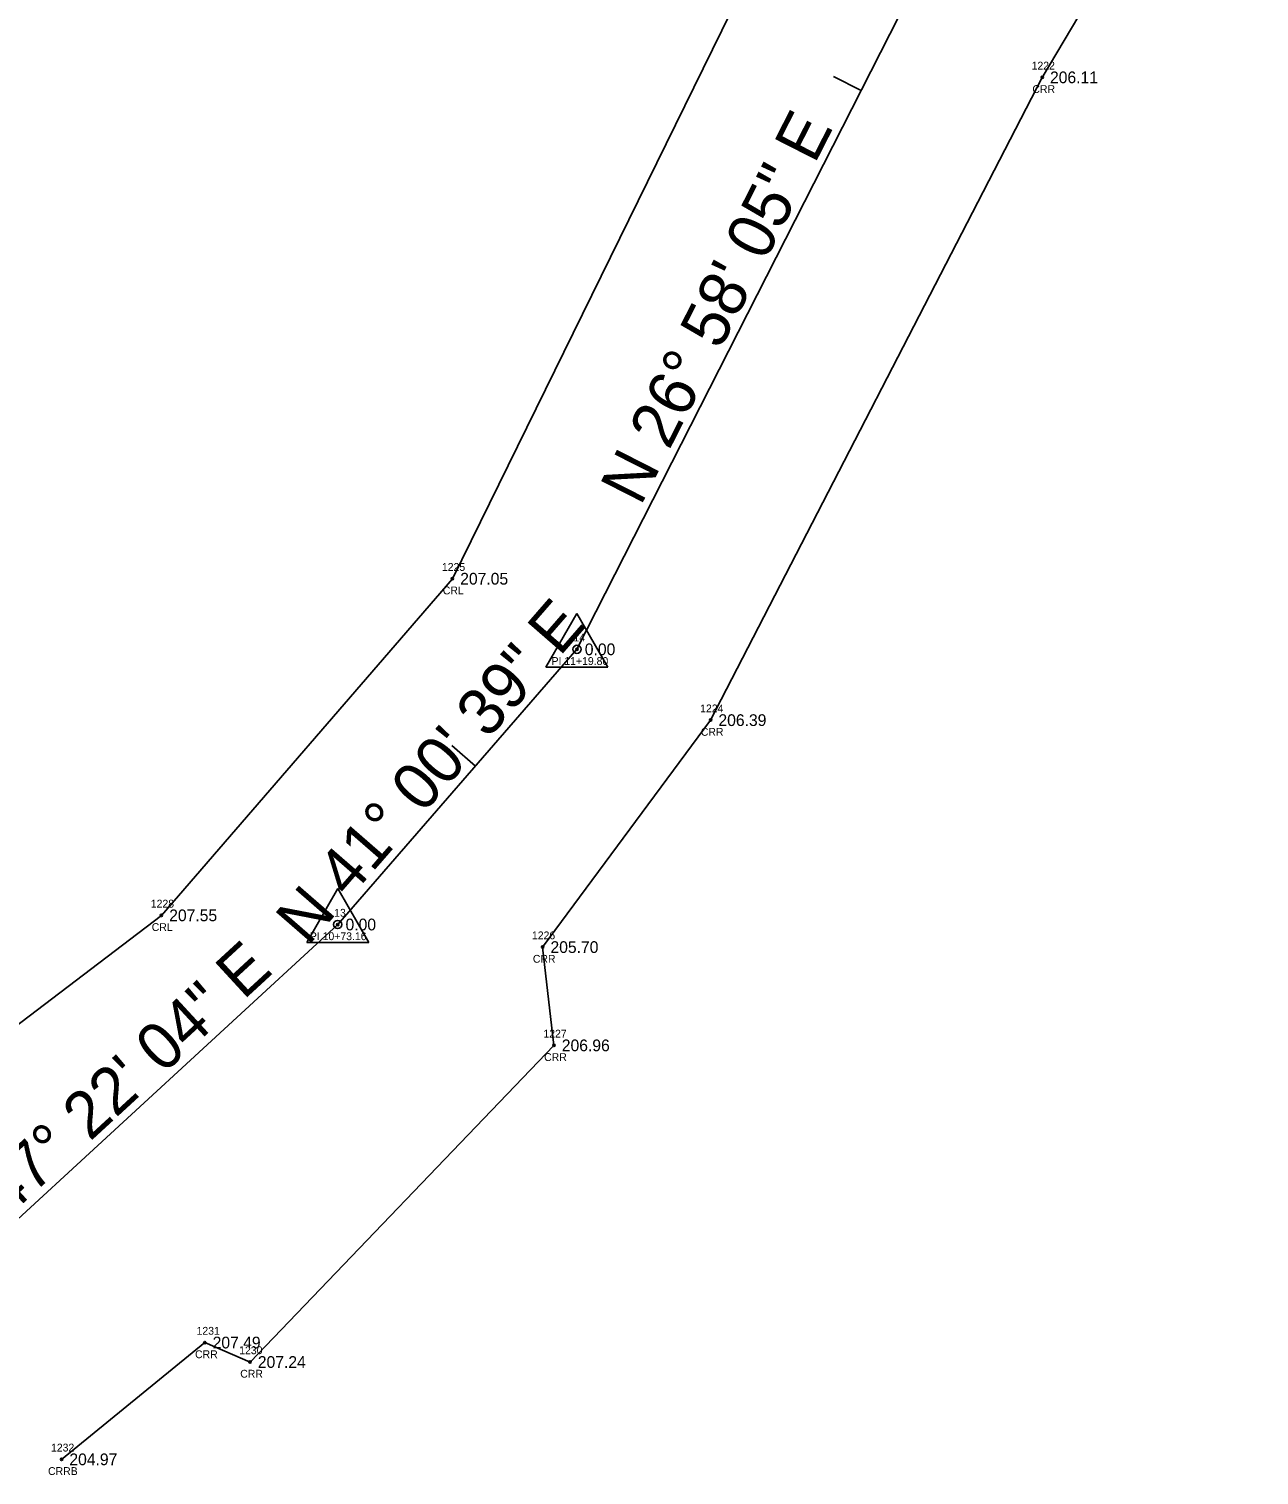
# Model space of a CAD drawing. Extents: x 2259948 to 2261336, y 1064647 to 1065986.
# Drawn here: x 2260519.2 to 2260676.5, y 1064647.3 to 1064832.3 of the extents above; entities that cross this region are included whole.
import ezdxf

# ---------------------------------------------------------------- set-up
doc = ezdxf.new("R2010")
doc.units = 0
for name, color, linetype in [('RD_EX_H2O', 7, 'Continuous'), ('RD_EX_H2O_txCode', 7, 'Continuous'), ('RD_EX_TX_H2O_ELEV', 7, 'Continuous'), ('RD_HC_Cl', 7, 'Continuous'), ('RD_HC_Data', 7, 'Continuous'), ('RD_HC_Data_Tic', 7, 'Continuous'), ('RD_HC_Survey_ELEV', 7, 'Continuous'), ('RD_HC_txCode', 7, 'Continuous'), ('RD_SMD_Locator', 7, 'Continuous')]:
    doc.layers.add(name, color=color, linetype=linetype)

msp = doc.modelspace()

# ---------------------------------------------------------------- linework, layer by layer
at = {"layer": 'RD_EX_H2O'}
for points in [[(2260766.96, 1065089.79), (2260769.94, 1065084.22), (2260769.59, 1065075.21), (2260766.59, 1065063.56), (2260718.2, 1065001.51), (2260666.03, 1064928.94), (2260617.31, 1064851.47), (2260573.34, 1064761.94), (2260536.11, 1064718.88), (2260488.15, 1064682.39)], [(2260814.11, 1065053.05), (2260812.59, 1065051.01), (2260806.25, 1065051.8), (2260750.48, 1064985.06), (2260697.06, 1064907.27), (2260648.8, 1064826.07), (2260606.38, 1064743.85), (2260584.89, 1064714.82), (2260586.34, 1064702.25), (2260547.45, 1064661.75), (2260541.67, 1064664.24), (2260523.34, 1064649.3)]]:
    msp.add_lwpolyline(points, dxfattribs=at)
at = {"layer": 'RD_HC_Cl'}
for p, q in [((2260589.28, 1064752.91), (2260632.73, 1064838.31)), ((2260558.67, 1064717.71), (2260589.28, 1064752.91)), ((2260504.85, 1064668.17), (2260558.67, 1064717.71))]:
    msp.add_line(p, q, dxfattribs=at)
at = {"layer": 'RD_HC_Data'}
for p, q in [((2260585.31, 1064750.62), (2260589.28, 1064757.5)), ((2260589.28, 1064757.5), (2260593.25, 1064750.62)), ((2260585.31, 1064750.62), (2260593.25, 1064750.62)), ((2260554.7, 1064715.42), (2260558.67, 1064722.3)), ((2260558.67, 1064722.3), (2260562.64, 1064715.42)), ((2260554.7, 1064715.42), (2260562.64, 1064715.42))]:
    msp.add_line(p, q, dxfattribs=at)
for centre in [(2260589.28, 1064752.91), (2260558.67, 1064717.71)]:
    msp.add_circle(centre, 0.529, dxfattribs=at)
at = {"layer": 'RD_HC_Data_Tic'}
for p, q in [((2260625.65, 1064824.39), (2260622.08, 1064826.2)), ((2260576.28, 1064737.97), (2260573.26, 1064740.59))]:
    msp.add_line(p, q, dxfattribs=at)
at = {"layer": 'RD_SMD_Locator'}
for centre in [(2260648.8, 1064826.07), (2260573.34, 1064761.94), (2260589.28, 1064752.91), (2260606.38, 1064743.85), (2260536.11, 1064718.88), (2260558.67, 1064717.71), (2260584.89, 1064714.82), (2260586.34, 1064702.25), (2260541.67, 1064664.24), (2260547.45, 1064661.75), (2260523.34, 1064649.3)]:
    msp.add_circle(centre, 0.15, dxfattribs=at)

# ---------------------------------------------------------------- texts
at = {"layer": 'RD_EX_H2O_txCode'}
for s, p in [('1222', (2260647.45, 1064827.07)), ('CRR', (2260647.55, 1064824.07)), ('1225', (2260572, 1064762.94)), ('CRL', (2260572.12, 1064759.94)), ('1224', (2260605.04, 1064744.85)), ('CRR', (2260605.13, 1064741.85)), ('1228', (2260534.76, 1064719.88)), ('CRL', (2260534.88, 1064716.88)), ('1226', (2260583.52, 1064715.82)), ('CRR', (2260583.64, 1064712.82)), ('1227', (2260584.99, 1064703.25)), ('CRR', (2260585.08, 1064700.25)), ('1231', (2260540.61, 1064665.24)), ('CRR', (2260540.42, 1064662.24)), ('1230', (2260546.07, 1064662.75)), ('CRR', (2260546.2, 1064659.75)), ('1232', (2260521.99, 1064650.3)), ('CRRB', (2260521.61, 1064647.3))]:
    msp.add_text(s, height=1, dxfattribs=at).set_placement(p)
at = {"layer": 'RD_EX_TX_H2O_ELEV'}
for s, p in [('206.11', (2260649.8, 1064825.32)), ('207.05', (2260574.34, 1064761.19)), ('206.39', (2260607.38, 1064743.1)), ('207.55', (2260537.11, 1064718.13)), ('205.70', (2260585.89, 1064714.07)), ('206.96', (2260587.34, 1064701.5)), ('207.49', (2260542.67, 1064663.49)), ('207.24', (2260548.45, 1064661)), ('204.97', (2260524.34, 1064648.55))]:
    msp.add_text(s, height=1.5, dxfattribs=at).set_placement(p)
at = {"layer": 'RD_HC_Data'}
for s, rotation, p in [('N 26%%d 58\' 05" E', 63.0319, (2260597.42, 1064771.13)), ('N 41%%d 00\' 39" E', 48.9892, (2260554.86, 1064714.86)), ('N 47%%d 22\' 04" E', 42.6323, (2260510.5, 1064674.73))]:
    msp.add_text(s, height=6, rotation=rotation, dxfattribs=at).set_placement(p)
at = {"layer": 'RD_HC_Survey_ELEV'}
for p in [(2260590.28, 1064752.16), (2260559.67, 1064716.96)]:
    msp.add_text('0.00', height=1.5, dxfattribs=at).set_placement(p)
at = {"layer": 'RD_HC_txCode'}
for s, p in [('14', (2260588.83, 1064753.91)), ('PI 11+19.80', (2260586.03, 1064750.91)), ('13', (2260558.22, 1064718.71)), ('PI 10+73.16', (2260555.11, 1064715.71))]:
    msp.add_text(s, height=1, dxfattribs=at).set_placement(p)

doc.saveas('drawing.dxf')
